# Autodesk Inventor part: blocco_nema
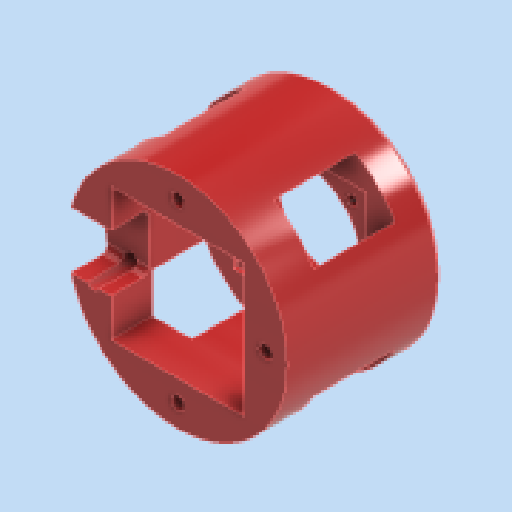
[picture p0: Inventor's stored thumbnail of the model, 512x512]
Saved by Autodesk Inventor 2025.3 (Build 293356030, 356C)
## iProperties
Created: 2026-01
Part Number: blocco_nema
Material: Plastica ABS
Document SubType Name: Modeling
Designer: Ryzen5700u
Density: 1.06 g/cm^3
Appearance: Rosso
Author: Ryzen5700u
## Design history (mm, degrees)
sketch "Schizzo1"
  geometry: C1 r 18.25 at (0, 0); C2 r 35 at (0, 0); 1 further point
  constraints: 2 centre point, 2 coincident
  dimensions: "d0" = 36.5 diameter of C1; "d1" = 70 diameter of C2
extrude "Estrusione1" new body sketch "Schizzo1" distance "d2" = 10; taper "d3" = 0 deg
sketch "Schizzo2"
  geometry: L1 (21.1, 21.1)-(-21.1, 21.1); L2 (-21.1, 21.1)-(-21.1, -21.1); L3 (-21.1, -21.1)-(21.1, -21.1); L4 (21.1, -21.1)-(21.1, 21.1); L5 (21.1, 21.1)-(-21.1, -21.1); L6 (-21.1, 21.1)-(21.1, -21.1); C1 r 35 at (0, 0) reference; 1 further point
  constraints: 12 end point, 2 midpoint, 2 parallel, 1 horizontal, 1 perpendicular
  dimensions: "d4" = 42.2 distance of L3.end L2.end; "d5" = 42.2 distance of L2.end L1.end
extrude "Estrusione2" join sketch "Schizzo2" distance "d6" = 40; taper "d7" = 0 deg
sketch "Schizzo3"
  geometry: C1 r 3.25 at (-15.5, -15.5) reference; C2 r 3.25 at (15.5, -15.5) reference; C3 r 3.25 at (15.5, 15.5) reference; C4 r 3.25 at (-15.5, 15.5) reference; 1 further point
hole "Foro1" sketch "Schizzo3" at (-15.5, -15.5), (15.5, -15.5), (15.5, 15.5), (-15.5, 15.5) diameter "d8" = 3.2; stored, may be unused: countersink angle "d12" = 82 deg, drill point angle "d14" = 118 deg; dims "d9" = 6, "d10" = 5.8, "d11" = 3.4, "d13" = 8
node "Piano di lavoro1"
sketch "Schizzo4"
  geometry: L1 (-9, -62)-(9, -62); L2 (9, -62)-(9, -38); L3 (9, -38)-(-9, -38); L4 (-9, -38)-(-9, -62); L5 (-21.1, -50)-(21.1, -50) reference; L6 (-9, -62)-(9, -38); L7 (9, -62)-(-9, -38); L8 (-35, -50)-(35, -50) reference; 4 further points
  constraints: 12 end point, 3 midpoint, 2 parallel, 1 horizontal, 1 perpendicular
  dimensions: "d15" = 18 distance of L3.end L2.end; "d16" = 24 distance of L2.end L1.end
extrude "Estrusione3" cut sketch "Schizzo4" distance "d17" = 40; taper "d18" = 0 deg
chamfer "Smusso1" distance "d19" = 2; stored, may be unused: second distance "d20" = 2, angle "d21" = 45 deg
sketch "Schizzo5"
  geometry: L1 (0, 0)-(46.114, 0); A1 r 28 centre (0, 0) between (0, 28) and (26.833, -8); 1 further point
  constraints: 2 end point, 2 point on circle, 1 centre point, 1 coincident, 1 horizontal
  dimensions: "d22" = 56 diameter of A1; "d40" = 8 distance from line of L1 A1.end
hole "Foro2" sketch "Schizzo5" diameter "d23" = 4.3; stored, may be unused: countersink angle "d27" = 90 deg, drill point angle "d29" = 118 deg; dims "d24" = 6, "d25" = 8, "d26" = 25, "d28" = 8
pattern_circular "Serie circolare1" dims angle "d31" = 360 deg
hole "Foro3" sketch "Schizzo5" diameter "d33" = 4.3; stored, may be unused: countersink angle "d37" = 90 deg, drill point angle "d39" = 118 deg; dims "d34" = 6, "d35" = 8, "d36" = 27, "d38" = 8
node "Piano di lavoro2"
fillet "Raccordo1" dims "d50" = 2
sketch "Schizzo6"
  geometry: L1 (18, 0)-(30, 0); L2 (10, 0)-(50, 0) reference; L3 (18, -7)-(30, -7); L4 (30, 7)-(18, 7); L5 (10, 18.25)-(10, -18.25) reference; L6 (11, 9)-(37, 9); L7 (37, 9)-(37, -9); L8 (37, -9)-(11, -9); L9 (11, -9)-(11, 9); L10 (11, 9)-(37, -9); L11 (37, 9)-(11, -9); A1 r 7 centre (18, 0) between (18, 7) and (18, -7); A2 r 7 centre (30, 0) between (30, -7) and (30, 7); 4 further points
  constraints: 20 end point, 4 midpoint, 4 point on circle, 4 tangent, 3 parallel, 2 centre point, 1 horizontal, 1 perpendicular, 1 point on line
  dimensions: "d42" = 12 distance of L4.start L4.end; "d48" = 14 distance from line of L5 point (24, 0); "d49" = 7 radius of A2; "d51" = 18 distance of L6.end L7.end
extrude "Estrusione4" cut sketch "Schizzo6" stored distance "d43" = 120; taper "d44" = 0 deg
pattern_circular "Serie circolare3" dims angle "d53" = 360 deg
node "Solido1"
node "Riferimento1"
node "Riferimento2"
node "Riferimento3"
node "Riferimento4"
other parameters: "d41" = 45 deg
